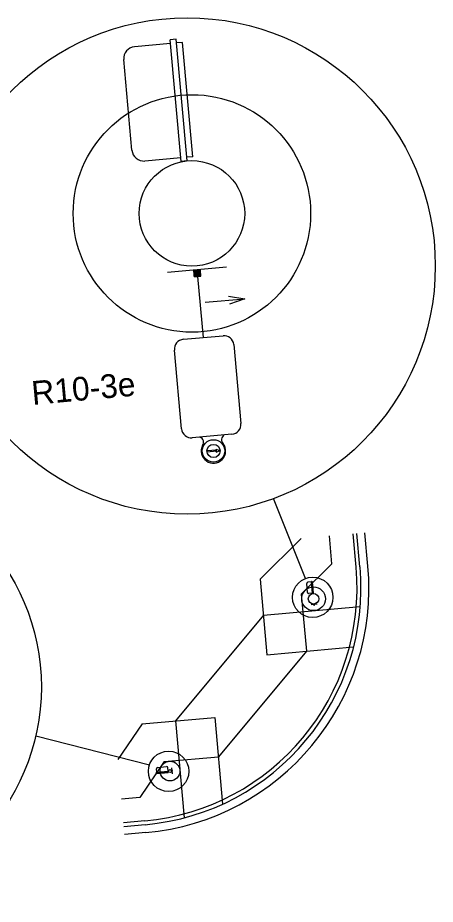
# Model space of a CAD drawing. Extents: x 1277218 to 1279252, y 196860 to 197529.
# Drawn here: x 1279120.6 to 1279201.3, y 197012.4 to 197183.7 of the extents above; entities that cross this region are included whole.
import ezdxf

# ---------------------------------------------------------------- set-up
doc = ezdxf.new("R2010")
doc.units = 0
doc.layers.add('S_EDGE_PAVEMENT', color=7, linetype='Continuous')

msp = doc.modelspace()

# ---------------------------------------------------------------- linework, layer by layer
at = {"layer": 'S_EDGE_PAVEMENT'}
for p, q in [((1279151.24, 197179.53), (1279150.1, 197179.43)), ((1279152.23, 197155.94), (1279150.1, 197179.43)), ((1279153.37, 197156.04), (1279151.24, 197179.53)), ((1279152.45, 197178.94), (1279151.3, 197178.84)), ((1279154.45, 197156.84), (1279152.45, 197178.94)), ((1279150.16, 197178.73), (1279143.18, 197178.1)), ((1279142.69, 197158.08), (1279141.1, 197175.61)), ((1279152.16, 197156.64), (1279145.18, 197156)), ((1279154.45, 197156.84), (1279153.31, 197156.74)), ((1279153.37, 197156.04), (1279152.23, 197155.94)), ((1279160.99, 197135.48), (1279149.57, 197134.45)), ((1279154.76, 197133.64), (1279154.64, 197134.91)), ((1279154.65, 197134.81), (1279154.74, 197134.92)), ((1279154.65, 197134.83), (1279154.72, 197134.91)), ((1279154.65, 197134.85), (1279154.7, 197134.91)), ((1279154.65, 197134.87), (1279154.68, 197134.91)), ((1279154.65, 197134.9), (1279154.66, 197134.91)), ((1279154.66, 197134.7), (1279154.85, 197134.93)), ((1279154.66, 197134.72), (1279154.83, 197134.92)), ((1279154.66, 197134.75), (1279154.81, 197134.92)), ((1279154.66, 197134.77), (1279154.78, 197134.92)), ((1279154.66, 197134.79), (1279154.76, 197134.92)), ((1279154.67, 197134.59), (1279154.96, 197134.94)), ((1279154.67, 197134.62), (1279154.94, 197134.93)), ((1279154.67, 197134.64), (1279154.91, 197134.93)), ((1279154.67, 197134.66), (1279154.89, 197134.93)), ((1279154.67, 197134.68), (1279154.87, 197134.93)), ((1279154.68, 197134.47), (1279155.09, 197134.95)), ((1279154.68, 197134.49), (1279155.07, 197134.95)), ((1279154.68, 197134.51), (1279155.04, 197134.94)), ((1279154.68, 197134.53), (1279155.02, 197134.94)), ((1279154.68, 197134.55), (1279155, 197134.94)), ((1279154.68, 197134.57), (1279154.98, 197134.94)), ((1279154.69, 197134.36), (1279155.19, 197134.96)), ((1279154.69, 197134.38), (1279155.17, 197134.95)), ((1279154.69, 197134.4), (1279155.15, 197134.95)), ((1279154.69, 197134.42), (1279155.13, 197134.95)), ((1279154.69, 197134.44), (1279155.11, 197134.95)), ((1279154.7, 197134.25), (1279155.3, 197134.97)), ((1279154.7, 197134.27), (1279155.28, 197134.96)), ((1279154.7, 197134.29), (1279155.26, 197134.96)), ((1279154.7, 197134.31), (1279155.24, 197134.96)), ((1279154.7, 197134.34), (1279155.22, 197134.96)), ((1279154.71, 197134.14), (1279155.41, 197134.98)), ((1279154.71, 197134.16), (1279155.39, 197134.97)), ((1279154.71, 197134.18), (1279155.37, 197134.97)), ((1279154.71, 197134.21), (1279155.35, 197134.97)), ((1279154.71, 197134.23), (1279155.32, 197134.97)), ((1279154.72, 197134.03), (1279155.52, 197134.99)), ((1279154.72, 197134.06), (1279155.5, 197134.98)), ((1279154.72, 197134.08), (1279155.47, 197134.98)), ((1279154.72, 197134.1), (1279155.45, 197134.98)), ((1279154.72, 197134.12), (1279155.43, 197134.98)), ((1279154.73, 197133.93), (1279155.63, 197135)), ((1279154.73, 197133.95), (1279155.6, 197134.99)), ((1279154.73, 197133.97), (1279155.58, 197134.99)), ((1279154.73, 197133.99), (1279155.56, 197134.99)), ((1279154.73, 197134.01), (1279155.54, 197134.99)), ((1279154.74, 197133.82), (1279155.73, 197135.01)), ((1279154.74, 197133.84), (1279155.71, 197135)), ((1279154.74, 197133.86), (1279155.69, 197135)), ((1279154.74, 197133.88), (1279155.67, 197135)), ((1279154.74, 197133.9), (1279155.65, 197135)), ((1279154.75, 197133.71), (1279155.84, 197135.02)), ((1279154.75, 197133.73), (1279155.82, 197135.01)), ((1279154.75, 197133.75), (1279155.8, 197135.01)), ((1279154.75, 197133.78), (1279155.78, 197135.01)), ((1279154.75, 197133.8), (1279155.75, 197135.01)), ((1279154.76, 197133.65), (1279155.91, 197135.02)), ((1279154.76, 197133.67), (1279155.88, 197135.02)), ((1279154.76, 197133.69), (1279155.86, 197135.02)), ((1279154.77, 197133.64), (1279155.92, 197135.01)), ((1279154.79, 197133.64), (1279155.92, 197134.99)), ((1279154.82, 197133.64), (1279155.92, 197134.97)), ((1279154.84, 197133.64), (1279155.92, 197134.94)), ((1279154.86, 197133.65), (1279155.92, 197134.92)), ((1279154.88, 197133.65), (1279155.93, 197134.9)), ((1279154.9, 197133.65), (1279155.93, 197134.88)), ((1279154.92, 197133.65), (1279155.93, 197134.86)), ((1279154.94, 197133.65), (1279155.93, 197134.84)), ((1279154.97, 197133.66), (1279155.93, 197134.82)), ((1279154.99, 197133.66), (1279155.94, 197134.79)), ((1279155.01, 197133.66), (1279155.94, 197134.77)), ((1279155.03, 197133.66), (1279155.94, 197134.75)), ((1279155.05, 197133.66), (1279155.94, 197134.73)), ((1279155.07, 197133.67), (1279155.94, 197134.71)), ((1279155.1, 197133.67), (1279155.95, 197134.69)), ((1279155.12, 197133.67), (1279155.95, 197134.66)), ((1279155.14, 197133.67), (1279155.95, 197134.64)), ((1279155.16, 197133.67), (1279155.95, 197134.62)), ((1279155.18, 197133.68), (1279155.95, 197134.6)), ((1279155.2, 197133.68), (1279155.95, 197134.58)), ((1279155.22, 197133.68), (1279155.96, 197134.56)), ((1279155.25, 197133.68), (1279155.96, 197134.54)), ((1279155.27, 197133.68), (1279155.96, 197134.51)), ((1279155.29, 197133.69), (1279155.96, 197134.49)), ((1279155.31, 197133.69), (1279155.96, 197134.47)), ((1279155.33, 197133.69), (1279155.97, 197134.45)), ((1279155.35, 197133.69), (1279155.97, 197134.43)), ((1279155.38, 197133.69), (1279155.97, 197134.41)), ((1279155.4, 197133.69), (1279155.97, 197134.38)), ((1279155.42, 197133.7), (1279155.97, 197134.36)), ((1279156.03, 197133.75), (1279155.91, 197135.02)), ((1279154.76, 197133.64), (1279156.03, 197133.75)), ((1279155.39, 197133.69), (1279156.46, 197121.91)), ((1279155.44, 197133.7), (1279155.98, 197134.34)), ((1279155.46, 197133.7), (1279155.98, 197134.32)), ((1279155.48, 197133.7), (1279155.98, 197134.3)), ((1279155.5, 197133.7), (1279155.98, 197134.28)), ((1279155.53, 197133.71), (1279155.98, 197134.26)), ((1279155.55, 197133.71), (1279155.99, 197134.23)), ((1279155.57, 197133.71), (1279155.99, 197134.21)), ((1279155.59, 197133.71), (1279155.99, 197134.19)), ((1279155.61, 197133.71), (1279155.99, 197134.17)), ((1279155.63, 197133.72), (1279155.99, 197134.15)), ((1279155.66, 197133.72), (1279156, 197134.13)), ((1279155.68, 197133.72), (1279156, 197134.1)), ((1279155.7, 197133.72), (1279156, 197134.08)), ((1279155.72, 197133.72), (1279156, 197134.06)), ((1279155.74, 197133.73), (1279156, 197134.04)), ((1279155.76, 197133.73), (1279156.01, 197134.02)), ((1279155.79, 197133.73), (1279156.01, 197134)), ((1279155.81, 197133.73), (1279156.01, 197133.98)), ((1279155.83, 197133.73), (1279156.01, 197133.95)), ((1279155.85, 197133.74), (1279156.01, 197133.93)), ((1279155.87, 197133.74), (1279156.02, 197133.91)), ((1279155.89, 197133.74), (1279156.02, 197133.89)), ((1279155.91, 197133.74), (1279156.02, 197133.87)), ((1279155.94, 197133.74), (1279156.02, 197133.85)), ((1279155.96, 197133.75), (1279156.02, 197133.82)), ((1279155.98, 197133.75), (1279156.03, 197133.8)), ((1279156, 197133.75), (1279156.03, 197133.78)), ((1279156.02, 197133.75), (1279156.03, 197133.76)), ((1279156.84, 197128.7), (1279164.51, 197129.4)), ((1279152.63, 197121.56), (1279160.3, 197122.25)), ((1279152.28, 197104.24), (1279150.9, 197119.48)), ((1279162.37, 197120.52), (1279163.76, 197105.28)), ((1279162.02, 197103.21), (1279154.35, 197102.51)), ((1279159.09, 197100.14), (1279157.18, 197099.97)), ((1279158.92, 197100.32), (1279159.72, 197100.08)), ((1279159.09, 197100.14), (1279158.92, 197100.32)), ((1279157.18, 197099.97), (1279157.2, 197099.74)), ((1279159.11, 197099.91), (1279157.2, 197099.74)), ((1279158.98, 197099.71), (1279159.72, 197100.08)), ((1279158.98, 197099.71), (1279159.11, 197099.91)), ((1279176.27, 197075.34), (1279170.05, 197090.76)), ((1279167.47, 197075.22), (1279175.43, 197083.06)), ((1279181.36, 197078.17), (1279180.88, 197083.55)), ((1279186.03, 197077.52), (1279185.45, 197083.97)), ((1279186.79, 197077.59), (1279186.21, 197084.04)), ((1279188.32, 197077.73), (1279187.73, 197084.17)), ((1279175.42, 197072.31), (1279181.36, 197078.17)), ((1279167.47, 197075.22), (1279168.8, 197060.6)), ((1279177.39, 197074.68), (1279176.69, 197074.62)), ((1279177.5, 197074.76), (1279177.39, 197074.75)), ((1279177.6, 197072.4), (1279177.39, 197074.75)), ((1279177.71, 197072.41), (1279177.5, 197074.76)), ((1279177.62, 197074.7), (1279177.51, 197074.69)), ((1279177.82, 197072.49), (1279177.62, 197074.7)), ((1279176.65, 197072.62), (1279176.49, 197074.37)), ((1279175.42, 197072.31), (1279176.42, 197061.29)), ((1279177.59, 197072.47), (1279176.9, 197072.41)), ((1279177.71, 197072.41), (1279177.6, 197072.4)), ((1279177.82, 197072.49), (1279177.71, 197072.48)), ((1279168.11, 197068.22), (1279186.84, 197069.91)), ((1279178.48, 197070.36), (1279177.33, 197070.26)), ((1279177.85, 197070.17), (1279177.84, 197070.3)), ((1279177.84, 197070.26), (1279177.88, 197070.3)), ((1279177.84, 197070.27), (1279177.88, 197070.3)), ((1279177.84, 197070.27), (1279177.87, 197070.3)), ((1279177.84, 197070.27), (1279177.87, 197070.3)), ((1279177.84, 197070.27), (1279177.87, 197070.3)), ((1279177.84, 197070.27), (1279177.87, 197070.3)), ((1279177.84, 197070.28), (1279177.87, 197070.3)), ((1279177.84, 197070.28), (1279177.86, 197070.3)), ((1279177.84, 197070.28), (1279177.86, 197070.3)), ((1279177.84, 197070.28), (1279177.86, 197070.3)), ((1279177.84, 197070.28), (1279177.86, 197070.3)), ((1279177.84, 197070.29), (1279177.86, 197070.3)), ((1279177.84, 197070.29), (1279177.85, 197070.3)), ((1279177.84, 197070.29), (1279177.85, 197070.3)), ((1279177.84, 197070.29), (1279177.85, 197070.3)), ((1279177.84, 197070.3), (1279177.85, 197070.3)), ((1279177.84, 197070.3), (1279177.84, 197070.3)), ((1279177.84, 197070.3), (1279177.84, 197070.3)), ((1279177.85, 197070.17), (1279177.97, 197070.31)), ((1279177.85, 197070.17), (1279177.97, 197070.31)), ((1279177.85, 197070.18), (1279177.97, 197070.31)), ((1279177.85, 197070.18), (1279177.96, 197070.31)), ((1279177.85, 197070.18), (1279177.96, 197070.31)), ((1279177.85, 197070.18), (1279177.96, 197070.31)), ((1279177.85, 197070.19), (1279177.96, 197070.31)), ((1279177.85, 197070.19), (1279177.95, 197070.31)), ((1279177.85, 197070.19), (1279177.95, 197070.31)), ((1279177.85, 197070.19), (1279177.95, 197070.31)), ((1279177.85, 197070.19), (1279177.95, 197070.31)), ((1279177.85, 197070.2), (1279177.95, 197070.31)), ((1279177.85, 197070.2), (1279177.94, 197070.31)), ((1279177.85, 197070.2), (1279177.94, 197070.31)), ((1279177.85, 197070.2), (1279177.94, 197070.31)), ((1279177.85, 197070.21), (1279177.94, 197070.31)), ((1279177.85, 197070.21), (1279177.94, 197070.31)), ((1279177.85, 197070.21), (1279177.93, 197070.31)), ((1279177.85, 197070.21), (1279177.93, 197070.31)), ((1279177.85, 197070.21), (1279177.93, 197070.31)), ((1279177.85, 197070.22), (1279177.93, 197070.31)), ((1279177.85, 197070.22), (1279177.92, 197070.31)), ((1279177.85, 197070.22), (1279177.92, 197070.31)), ((1279177.85, 197070.22), (1279177.92, 197070.31)), ((1279177.85, 197070.22), (1279177.92, 197070.31)), ((1279177.85, 197070.23), (1279177.92, 197070.31)), ((1279177.85, 197070.23), (1279177.91, 197070.31)), ((1279177.85, 197070.23), (1279177.91, 197070.31)), ((1279177.85, 197070.23), (1279177.91, 197070.31)), ((1279177.85, 197070.24), (1279177.91, 197070.31)), ((1279177.85, 197070.24), (1279177.91, 197070.31)), ((1279177.85, 197070.24), (1279177.9, 197070.31)), ((1279177.85, 197070.24), (1279177.9, 197070.31)), ((1279177.85, 197070.24), (1279177.9, 197070.31)), ((1279177.85, 197070.25), (1279177.9, 197070.31)), ((1279177.85, 197070.25), (1279177.89, 197070.31)), ((1279177.85, 197070.25), (1279177.89, 197070.31)), ((1279177.85, 197070.25), (1279177.89, 197070.31)), ((1279177.85, 197070.25), (1279177.89, 197070.31)), ((1279177.85, 197070.26), (1279177.89, 197070.31)), ((1279177.85, 197070.26), (1279177.88, 197070.3)), ((1279177.85, 197070.26), (1279177.88, 197070.3)), ((1279177.85, 197070.17), (1279177.98, 197070.19)), ((1279177.86, 197070.17), (1279177.97, 197070.31)), ((1279177.86, 197070.17), (1279177.97, 197070.31)), ((1279177.86, 197070.17), (1279177.97, 197070.3)), ((1279177.86, 197070.17), (1279177.97, 197070.3)), ((1279177.87, 197070.18), (1279177.97, 197070.3)), ((1279177.87, 197070.18), (1279177.97, 197070.3)), ((1279177.87, 197070.18), (1279177.97, 197070.3)), ((1279177.87, 197070.18), (1279177.97, 197070.29)), ((1279177.87, 197070.18), (1279177.97, 197070.29)), ((1279177.88, 197070.18), (1279177.97, 197070.29)), ((1279177.88, 197070.18), (1279177.97, 197070.29)), ((1279177.88, 197070.18), (1279177.97, 197070.29)), ((1279177.88, 197070.18), (1279177.97, 197070.28)), ((1279177.88, 197070.18), (1279177.97, 197070.28)), ((1279177.89, 197070.18), (1279177.97, 197070.28)), ((1279177.89, 197070.18), (1279177.97, 197070.28)), ((1279177.89, 197070.18), (1279177.97, 197070.27)), ((1279177.89, 197070.18), (1279177.97, 197070.27)), ((1279177.9, 197070.18), (1279177.97, 197070.27)), ((1279177.9, 197070.18), (1279177.97, 197070.27)), ((1279177.9, 197070.18), (1279177.97, 197070.27)), ((1279177.9, 197070.18), (1279177.97, 197070.26)), ((1279177.9, 197070.18), (1279177.97, 197070.26)), ((1279177.91, 197070.18), (1279177.97, 197070.26)), ((1279177.91, 197070.18), (1279177.97, 197070.26)), ((1279177.91, 197070.18), (1279177.97, 197070.26)), ((1279177.91, 197070.18), (1279177.97, 197070.25)), ((1279177.91, 197070.18), (1279177.97, 197070.25)), ((1279177.92, 197070.18), (1279177.97, 197070.25)), ((1279177.92, 197070.18), (1279177.97, 197070.25)), ((1279177.92, 197070.18), (1279177.97, 197070.24)), ((1279177.92, 197070.18), (1279177.97, 197070.24)), ((1279177.93, 197070.18), (1279177.98, 197070.24)), ((1279177.93, 197070.18), (1279177.98, 197070.24)), ((1279177.93, 197070.18), (1279177.98, 197070.24)), ((1279177.93, 197070.18), (1279177.98, 197070.23)), ((1279177.93, 197070.18), (1279177.98, 197070.23)), ((1279177.94, 197070.18), (1279177.98, 197070.23)), ((1279177.94, 197070.18), (1279177.98, 197070.23)), ((1279177.94, 197070.18), (1279177.98, 197070.23)), ((1279177.94, 197070.18), (1279177.98, 197070.22)), ((1279177.94, 197070.18), (1279177.98, 197070.22)), ((1279177.95, 197070.18), (1279177.98, 197070.22)), ((1279177.95, 197070.18), (1279177.98, 197070.22)), ((1279177.95, 197070.18), (1279177.98, 197070.21)), ((1279177.95, 197070.18), (1279177.98, 197070.21)), ((1279177.96, 197070.18), (1279177.98, 197070.21)), ((1279177.96, 197070.18), (1279177.98, 197070.21)), ((1279177.96, 197070.18), (1279177.98, 197070.21)), ((1279177.96, 197070.18), (1279177.98, 197070.2)), ((1279177.96, 197070.18), (1279177.98, 197070.2)), ((1279177.98, 197070.19), (1279177.97, 197070.31)), ((1279177.97, 197070.18), (1279177.98, 197070.2)), ((1279177.97, 197070.18), (1279177.98, 197070.2)), ((1279177.97, 197070.19), (1279177.98, 197070.19)), ((1279177.97, 197070.18), (1279177.98, 197070.19)), ((1279177.97, 197070.18), (1279177.98, 197070.19)), ((1279177.98, 197070.19), (1279177.98, 197070.19)), ((1279177.98, 197070.19), (1279177.98, 197070.19)), ((1279168.11, 197068.22), (1279151.09, 197047.8)), ((1279176.42, 197061.29), (1279159.4, 197040.87)), ((1279168.8, 197060.6), (1279185.56, 197062.12)), ((1279144.65, 197047.22), (1279139.95, 197040.32)), ((1279144.65, 197047.22), (1279158.71, 197048.49)), ((1279151.09, 197047.8), (1279152.78, 197029.07)), ((1279158.71, 197048.49), (1279160.22, 197031.73)), ((1279146.06, 197039.23), (1279124.08, 197044.88)), ((1279148.94, 197039.93), (1279159.4, 197040.87)), ((1279148.94, 197039.93), (1279144.23, 197033.02)), ((1279147.48, 197037.87), (1279147.42, 197038.57)), ((1279147.63, 197038.82), (1279149.38, 197038.98)), ((1279149.69, 197038.07), (1279149.63, 197038.77)), ((1279150.36, 197038.71), (1279150.46, 197037.57)), ((1279147.41, 197037.87), (1279149.76, 197038.08)), ((1279147.42, 197037.75), (1279147.41, 197037.87)), ((1279147.42, 197037.75), (1279149.77, 197037.97)), ((1279147.5, 197037.64), (1279147.49, 197037.76)), ((1279147.5, 197037.64), (1279149.71, 197037.84)), ((1279149.71, 197037.84), (1279149.7, 197037.96)), ((1279149.77, 197037.97), (1279149.76, 197038.08)), ((1279150.53, 197038.21), (1279150.4, 197038.2)), ((1279150.4, 197038.17), (1279150.44, 197038.21)), ((1279150.4, 197038.17), (1279150.44, 197038.2)), ((1279150.4, 197038.17), (1279150.43, 197038.2)), ((1279150.4, 197038.17), (1279150.43, 197038.2)), ((1279150.4, 197038.17), (1279150.43, 197038.2)), ((1279150.4, 197038.18), (1279150.43, 197038.2)), ((1279150.4, 197038.18), (1279150.42, 197038.2)), ((1279150.4, 197038.18), (1279150.42, 197038.2)), ((1279150.4, 197038.18), (1279150.42, 197038.2)), ((1279150.4, 197038.19), (1279150.42, 197038.2)), ((1279150.4, 197038.19), (1279150.42, 197038.2)), ((1279150.4, 197038.19), (1279150.41, 197038.2)), ((1279150.4, 197038.19), (1279150.41, 197038.2)), ((1279150.4, 197038.19), (1279150.41, 197038.2)), ((1279150.4, 197038.2), (1279150.41, 197038.2)), ((1279150.4, 197038.2), (1279150.41, 197038.2)), ((1279150.4, 197038.2), (1279150.4, 197038.2)), ((1279150.41, 197038.08), (1279150.53, 197038.21)), ((1279150.41, 197038.08), (1279150.53, 197038.21)), ((1279150.41, 197038.08), (1279150.53, 197038.21)), ((1279150.41, 197038.08), (1279150.52, 197038.21)), ((1279150.41, 197038.08), (1279150.52, 197038.21)), ((1279150.41, 197038.08), (1279150.52, 197038.21)), ((1279150.41, 197038.09), (1279150.52, 197038.21)), ((1279150.41, 197038.09), (1279150.52, 197038.21)), ((1279150.41, 197038.09), (1279150.51, 197038.21)), ((1279150.41, 197038.09), (1279150.51, 197038.21)), ((1279150.41, 197038.09), (1279150.51, 197038.21)), ((1279150.41, 197038.1), (1279150.51, 197038.21)), ((1279150.41, 197038.1), (1279150.5, 197038.21)), ((1279150.41, 197038.1), (1279150.5, 197038.21)), ((1279150.41, 197038.1), (1279150.5, 197038.21)), ((1279150.41, 197038.11), (1279150.5, 197038.21)), ((1279150.41, 197038.11), (1279150.5, 197038.21)), ((1279150.41, 197038.11), (1279150.49, 197038.21)), ((1279150.41, 197038.11), (1279150.49, 197038.21)), ((1279150.41, 197038.11), (1279150.49, 197038.21)), ((1279150.41, 197038.12), (1279150.49, 197038.21)), ((1279150.41, 197038.12), (1279150.49, 197038.21)), ((1279150.41, 197038.12), (1279150.48, 197038.21)), ((1279150.41, 197038.12), (1279150.48, 197038.21)), ((1279150.41, 197038.12), (1279150.48, 197038.21)), ((1279150.41, 197038.13), (1279150.48, 197038.21)), ((1279150.41, 197038.13), (1279150.47, 197038.21)), ((1279150.41, 197038.13), (1279150.47, 197038.21)), ((1279150.41, 197038.13), (1279150.47, 197038.21)), ((1279150.41, 197038.14), (1279150.47, 197038.21)), ((1279150.41, 197038.14), (1279150.47, 197038.21)), ((1279150.41, 197038.14), (1279150.46, 197038.21)), ((1279150.41, 197038.14), (1279150.46, 197038.21)), ((1279150.41, 197038.14), (1279150.46, 197038.21)), ((1279150.41, 197038.15), (1279150.46, 197038.21)), ((1279150.41, 197038.15), (1279150.45, 197038.21)), ((1279150.41, 197038.15), (1279150.45, 197038.21)), ((1279150.41, 197038.15), (1279150.45, 197038.21)), ((1279150.41, 197038.16), (1279150.45, 197038.21)), ((1279150.41, 197038.16), (1279150.45, 197038.21)), ((1279150.41, 197038.16), (1279150.44, 197038.21)), ((1279150.41, 197038.16), (1279150.44, 197038.21)), ((1279150.41, 197038.16), (1279150.44, 197038.21)), ((1279150.54, 197038.09), (1279150.41, 197038.07)), ((1279150.42, 197038.08), (1279150.53, 197038.21)), ((1279150.42, 197038.08), (1279150.53, 197038.21)), ((1279150.42, 197038.08), (1279150.53, 197038.21)), ((1279150.42, 197038.08), (1279150.53, 197038.2)), ((1279150.43, 197038.08), (1279150.53, 197038.2)), ((1279150.43, 197038.08), (1279150.53, 197038.2)), ((1279150.43, 197038.08), (1279150.53, 197038.2)), ((1279150.43, 197038.08), (1279150.53, 197038.19)), ((1279150.43, 197038.08), (1279150.53, 197038.19)), ((1279150.44, 197038.08), (1279150.53, 197038.19)), ((1279150.44, 197038.08), (1279150.53, 197038.19)), ((1279150.44, 197038.08), (1279150.53, 197038.19)), ((1279150.44, 197038.08), (1279150.53, 197038.18)), ((1279150.44, 197038.08), (1279150.53, 197038.18)), ((1279150.45, 197038.08), (1279150.53, 197038.18)), ((1279150.45, 197038.08), (1279150.53, 197038.18)), ((1279150.45, 197038.08), (1279150.53, 197038.17)), ((1279150.45, 197038.08), (1279150.53, 197038.17)), ((1279150.46, 197038.08), (1279150.53, 197038.17)), ((1279150.46, 197038.08), (1279150.53, 197038.17)), ((1279150.46, 197038.08), (1279150.53, 197038.17)), ((1279150.46, 197038.08), (1279150.53, 197038.16)), ((1279150.46, 197038.08), (1279150.53, 197038.16)), ((1279150.47, 197038.08), (1279150.53, 197038.16)), ((1279150.47, 197038.08), (1279150.53, 197038.16)), ((1279150.47, 197038.08), (1279150.53, 197038.16)), ((1279150.47, 197038.08), (1279150.53, 197038.15)), ((1279150.48, 197038.08), (1279150.53, 197038.15)), ((1279150.48, 197038.08), (1279150.53, 197038.15)), ((1279150.48, 197038.08), (1279150.53, 197038.15)), ((1279150.48, 197038.08), (1279150.53, 197038.14)), ((1279150.48, 197038.08), (1279150.53, 197038.14)), ((1279150.49, 197038.08), (1279150.54, 197038.14)), ((1279150.49, 197038.08), (1279150.54, 197038.14)), ((1279150.49, 197038.08), (1279150.54, 197038.14)), ((1279150.49, 197038.08), (1279150.54, 197038.13)), ((1279150.49, 197038.08), (1279150.54, 197038.13)), ((1279150.5, 197038.08), (1279150.54, 197038.13)), ((1279150.5, 197038.08), (1279150.54, 197038.13)), ((1279150.5, 197038.08), (1279150.54, 197038.13)), ((1279150.5, 197038.08), (1279150.54, 197038.12)), ((1279150.51, 197038.08), (1279150.54, 197038.12)), ((1279150.51, 197038.08), (1279150.54, 197038.12)), ((1279150.51, 197038.08), (1279150.54, 197038.12)), ((1279150.51, 197038.08), (1279150.54, 197038.11)), ((1279150.51, 197038.08), (1279150.54, 197038.11)), ((1279150.52, 197038.08), (1279150.54, 197038.11)), ((1279150.52, 197038.08), (1279150.54, 197038.11)), ((1279150.52, 197038.08), (1279150.54, 197038.11)), ((1279150.52, 197038.08), (1279150.54, 197038.1)), ((1279150.52, 197038.08), (1279150.54, 197038.1)), ((1279150.54, 197038.09), (1279150.53, 197038.21)), ((1279150.53, 197038.09), (1279150.54, 197038.1)), ((1279150.53, 197038.09), (1279150.54, 197038.1)), ((1279150.53, 197038.09), (1279150.54, 197038.1)), ((1279150.53, 197038.09), (1279150.54, 197038.09)), ((1279150.54, 197038.09), (1279150.54, 197038.09)), ((1279150.54, 197038.09), (1279150.54, 197038.09)), ((1279150.54, 197038.09), (1279150.54, 197038.09)), ((1279144.23, 197033.02), (1279140.64, 197032.7)), ((1279145.16, 197028.5), (1279141.05, 197028.13)), ((1279145.22, 197027.74), (1279141.12, 197027.36)), ((1279145.36, 197026.21), (1279141.26, 197025.84))]:
    msp.add_line(p, q, dxfattribs=at)
msp.add_lwpolyline([(1279161.39, 197129.88), (1279164.51, 197129.4), (1279161.53, 197128.36)], dxfattribs=at)
for centre, radius in [((1279153.38, 197135.73), 47.97), ((1279154.29, 197145.88), 22.95), ((1279154.29, 197145.88), 10.2), ((1279158.45, 197099.97), 2.17), ((1279158.45, 197099.97), 1.27), ((1279083.18, 197054.35), 41.99), ((1279177.65, 197071.68), 3.91), ((1279177.81, 197071.4), 2.29), ((1279177.81, 197071.4), 1.02), ((1279149.78, 197038.06), 3.91), ((1279150.05, 197038.11), 1.91), ((1279150.05, 197038.11), 0.287)]:
    msp.add_circle(centre, radius, dxfattribs=at)
for centre, radius, start, end in [((1279143.38, 197175.81), 2.29, 95.1779, 185.1779), ((1279144.97, 197158.29), 2.29, 185.1779, 275.1779), ((1279152.8, 197119.65), 1.91, 95.1779, 185.1779), ((1279160.47, 197120.35), 1.91, 5.1779, 95.1779), ((1279161.85, 197105.11), 1.91, 275.1779, 5.1779), ((1279154.18, 197104.42), 1.91, 185.1779, 275.1779), ((1279155.47, 197101.64), 1.07, 323.3751, 69.9823), ((1279161.08, 197102.15), 1.07, 120.3735, 226.9807), ((1279158.45, 197099.97), 2.36, 153.9181, 36.4377), ((1279158.45, 197099.97), 2.36, 153.9181, 232.6712), ((1279158.45, 197099.97), 2.36, 317.6845, 36.4377), ((1279141.08, 197073.45), 45.13, 275.1779, 5.1779), ((1279141.08, 197073.45), 45.9, 275.1779, 5.1779), ((1279141.08, 197073.45), 47.43, 275.1779, 5.1779), ((1279176.72, 197074.39), 0.229, 95.1779, 185.1779), ((1279176.87, 197072.64), 0.229, 185.1779, 275.1779), ((1279147.65, 197038.59), 0.229, 95.1779, 185.1779), ((1279149.4, 197038.75), 0.229, 5.1779, 95.1779)]:
    msp.add_arc(centre, radius, start, end, dxfattribs=at)

# ---------------------------------------------------------------- texts
msp.add_text('R10-3e', height=4.59, rotation=5.1779, dxfattribs=at).set_placement((1279123.48, 197108.86))

doc.saveas('drawing.dxf')
